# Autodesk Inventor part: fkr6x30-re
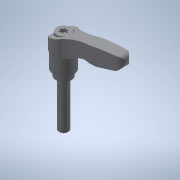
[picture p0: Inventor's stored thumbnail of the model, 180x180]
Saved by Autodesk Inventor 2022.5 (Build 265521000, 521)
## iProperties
Created: 2017-09
Part Number: fkr6x30-re
Material: 一般
Document SubType Name: Modeling
Designer: imaocorp
Density: 1 g/cm^3
Appearance: 既定
Author: imaocorp
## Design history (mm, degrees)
node "fkr6x30-re.x_t1"
node "fkr6x30-re"
node "Base1"
